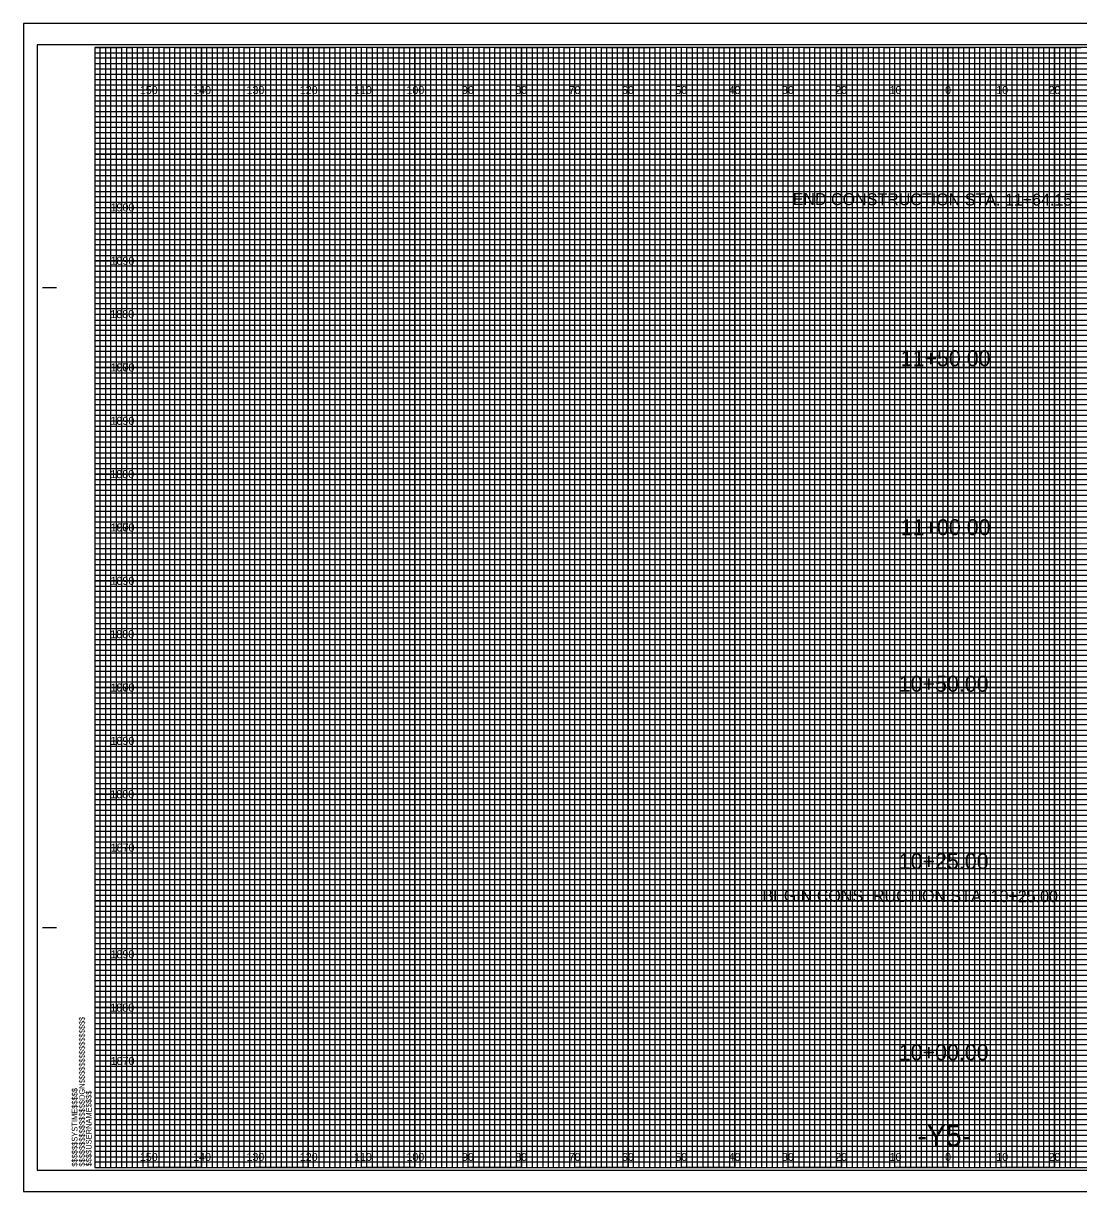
# Model space of a CAD drawing. Extents: x -13 to 323, y -4 to 214.
# Drawn here: x -13.4 to 184.5, y -4.5 to 214.5 of the extents above; entities that cross this region are included whole.
import ezdxf

# ---------------------------------------------------------------- set-up
doc = ezdxf.new("R2010")
doc.units = 0
for name, color, linetype in [('Prop XS Alignment Label', 7, 'Continuous'), ('Prop XS Elevation Labels', 7, 'Continuous'), ('Prop XS Offset Labels', 7, 'Continuous'), ('Prop XS SE Text', 7, 'Continuous'), ('Prop XS Station Labels', 7, 'Continuous'), ('Sheet Cross Section CELL', 7, 'Continuous'), ('Sheet Cross Section Grid Major CELL', 7, 'Continuous'), ('Sheet Cross Section Grid Middle CELL', 7, 'Continuous'), ('Sheet Cross Section Grid Minor 1 CELL', 7, 'Continuous'), ('Sheet Cross Section Grid Minor 2 CELL', 7, 'Continuous'), ('Sheet Cutting Line CELL', 7, 'Continuous'), ('Sheet DOT Grid CELL', 7, 'Continuous'), ('Sheet Plot Border Inside CELL', 7, 'Continuous'), ('Sheet Plot Border Outside CELL', 7, 'Continuous')]:
    doc.layers.add(name, color=color, linetype=linetype)

msp = doc.modelspace()

# ---------------------------------------------------------------- linework, layer by layer
at = {"layer": 'Sheet Cross Section CELL'}
for p, q in [((-9.8, 165), (-7.3, 165)), ((-9.7, 165), (-7.2, 165)), ((-9.8, 45), (-7.3, 45)), ((-9.7, 45), (-7.2, 45))]:
    msp.add_line(p, q, dxfattribs=at)
msp.add_lwpolyline([(320, 210), (0, 210), (0, 0), (320, 0)], close=True, dxfattribs=at)
at = {"layer": 'Sheet Cross Section Grid Major CELL'}
for p, q in [((10, 210), (0, 210)), ((10, 0), (10, 210)), ((30, 210), (20, 210)), ((20, 210), (20, 0)), ((30, 0), (30, 210)), ((50, 210), (40, 210)), ((40, 210), (40, 0)), ((50, 0), (50, 210)), ((70, 210), (60, 210)), ((60, 210), (60, 0)), ((70, 0), (70, 210)), ((90, 210), (80, 210)), ((80, 210), (80, 0)), ((90, 0), (90, 210)), ((110, 210), (100, 210)), ((100, 210), (100, 0)), ((110, 0), (110, 210)), ((130, 210), (120, 210)), ((120, 210), (120, 0)), ((130, 0), (130, 210)), ((150, 210), (140, 210)), ((140, 210), (140, 0)), ((150, 0), (150, 210)), ((170, 210), (160, 210)), ((160, 210), (160, 0)), ((170, 0), (170, 210)), ((190, 210), (180, 210)), ((180, 210), (180, 0)), ((20, 0), (10, 0)), ((40, 0), (30, 0)), ((60, 0), (50, 0)), ((80, 0), (70, 0)), ((100, 0), (90, 0)), ((120, 0), (110, 0)), ((140, 0), (130, 0)), ((160, 0), (150, 0)), ((180, 0), (170, 0))]:
    msp.add_line(p, q, dxfattribs=at)
for points in [[(0, 200), (320, 200), (320, 190), (0, 190)], [(0, 180), (320, 180), (320, 170), (0, 170)], [(0, 160), (320, 160), (320, 150), (0, 150)], [(0, 140), (320, 140), (320, 130), (0, 130)], [(0, 120), (320, 120), (320, 110), (0, 110)], [(0, 100), (320, 100), (320, 90), (0, 90)], [(0, 80), (320, 80), (320, 70), (0, 70)], [(0, 60), (320, 60), (320, 50), (0, 50)], [(0, 40), (320, 40), (320, 30), (0, 30)], [(0, 20), (320, 20), (320, 10), (0, 10)]]:
    msp.add_lwpolyline(points, dxfattribs=at)
at = {"layer": 'Sheet Cross Section Grid Middle CELL'}
for points in [[(0, 210), (5, 210), (5, 0), (15, 0), (15, 210), (25, 210), (25, 0), (35, 0), (35, 210), (45, 210), (45, 0), (55, 0), (55, 210), (65, 210), (65, 0), (75, 0), (75, 210), (85, 210), (85, 0), (95, 0), (95, 210), (105, 210), (105, 0), (115, 0), (115, 210), (125, 210), (125, 0), (135, 0), (135, 210), (145, 210), (145, 0), (155, 0), (155, 210), (165, 210), (165, 0), (175, 0), (175, 210), (185, 210)], [(0, 205), (275, 205)], [(0, 185), (320, 185), (320, 195), (0, 195)], [(0, 165), (320, 165), (320, 175), (0, 175)], [(0, 145), (320, 145), (320, 155), (0, 155)], [(0, 125), (320, 125), (320, 135), (0, 135)], [(0, 105), (320, 105), (320, 115), (0, 115)], [(0, 85), (320, 85), (320, 95), (0, 95)], [(0, 65), (320, 65), (320, 75), (0, 75)], [(0, 45), (320, 45), (320, 55), (0, 55)], [(0, 25), (320, 25), (320, 35), (0, 35)], [(0, 5), (320, 5), (320, 15), (0, 15)]]:
    msp.add_lwpolyline(points, dxfattribs=at)
at = {"layer": 'Sheet Cross Section Grid Minor 1 CELL'}
for p, q in [((0, 209), (260, 209)), ((260, 207.98), (0, 207.98)), ((0, 207.98), (0, 207)), ((0, 207), (260, 207)), ((260, 205.89), (0, 205.89)), ((0, 205.89), (0, 204)), ((0, 204), (320, 204))]:
    msp.add_line(p, q, dxfattribs=at)
for points in [[(0, 203), (270, 203), (320, 203), (320, 202), (0, 202)], [(0, 201), (320, 201), (320, 199), (0, 199)], [(0, 198), (320, 198), (320, 197), (0, 196.98)], [(0, 196), (320, 196), (320, 194), (0, 194)], [(0, 193), (320, 193), (320, 192), (0, 192)], [(0, 191), (320, 191), (320, 189), (0, 189)], [(0, 188), (320, 188), (320, 187), (0, 187)], [(0, 186), (320, 186), (320, 184), (0, 184)], [(0, 183), (320, 183), (320, 182), (0, 182)], [(0, 181), (320, 181), (320, 179), (0, 179)], [(0, 178), (320, 178), (320, 177), (0, 177)], [(0, 176), (320, 176), (320, 173.95), (320, 173), (320, 172), (0, 172)], [(0, 174), (320, 174), (320, 173), (0, 173)], [(0, 171), (320, 171), (320, 169), (0, 169.03)], [(0, 169.03), (320, 169), (320, 168), (0, 168)], [(0, 167), (320, 167), (320, 166), (0, 166)], [(0, 164), (320, 164), (320, 163), (0, 163)], [(0, 162), (320, 162), (320, 161), (0, 161)], [(-0.07, 158.89), (320, 158.89), (320, 157.88), (-0.07, 157.88)], [(0, 157), (320, 157), (320, 156), (0, 156)], [(0, 154), (320, 154), (320, 153), (0, 153)], [(0, 152), (320, 152), (320, 151), (0, 151)], [(0, 149), (320, 149), (320, 148), (0, 148)], [(0, 147), (320, 147), (320, 146), (0, 146)], [(0, 144), (320, 144), (320, 143), (0, 143)], [(0, 142), (320, 142), (320, 141), (0, 141)], [(0, 139), (320, 139), (319.99, 137.98), (0, 138)], [(0, 137), (320, 137), (320, 136), (0, 136)], [(0, 134), (320, 134), (320, 133), (0, 133)], [(0, 132), (320, 132), (320, 131), (0, 131)], [(0, 129), (320, 129), (320, 128), (0, 128)], [(0, 127), (320, 127), (320, 126), (0, 126)], [(0, 124), (320, 124), (320, 123), (0, 123)], [(0, 122), (320, 122), (320, 121), (0, 121)], [(0, 119), (320, 119), (320, 118), (0, 118)], [(0, 116.99), (320.07, 116.91), (320, 116), (0, 116)], [(0, 114), (320, 114), (320, 113), (0, 113)], [(0, 112), (320, 112), (320, 111), (0, 111)], [(0, 109), (320, 109), (320, 108), (0, 108)], [(0, 107), (320, 107), (320, 106), (0, 106)], [(0, 104), (320, 104), (320, 103), (0, 103)], [(0, 102), (320, 102), (320, 101), (0, 101)], [(0, 99), (320, 99), (320, 98), (0, 98)], [(0, 97), (320, 97), (320, 96), (0, 96)], [(0, 94), (320, 94), (320, 93), (0, 93)], [(0, 92), (320, 92), (320, 91), (0, 91)], [(0, 89), (320, 89), (320, 88), (0, 88)], [(0, 87), (320, 87), (320, 86), (0, 86)], [(0, 84), (320, 84), (320, 83), (0, 83)], [(0, 82), (320, 82), (320, 81), (0, 81)], [(0, 79), (320, 79), (319.99, 77.98), (0, 78)], [(0, 77), (320, 77), (320, 76), (0, 76)], [(0, 74), (320, 74), (320, 73), (0, 73)], [(0, 72), (320, 72), (320, 71), (0, 71)], [(0, 69), (320, 69), (320, 68), (0, 68)], [(0, 67), (320, 67), (320, 66), (0, 66)], [(0, 64), (320, 64), (320, 63), (0, 63)], [(0, 62), (320, 62), (320, 61), (0, 61)], [(0, 59), (320, 59), (320, 58), (0, 58)], [(0, 56.99), (320.07, 56.91), (320, 56), (0, 56)], [(0, 54), (320, 54), (320, 53), (0, 53)], [(0, 52), (320, 52), (320, 51), (0, 51)], [(0, 49), (320, 49), (320, 48), (0, 48)], [(0, 47), (320, 47), (320, 46), (0, 46)], [(0, 44), (320, 44), (320, 43), (0, 43)], [(0, 42), (320, 42), (320, 41), (0, 41)], [(0, 39), (320, 39), (320, 38), (0, 38)], [(0, 37), (320, 37), (320, 36), (0, 36)], [(0, 34), (320, 34), (320, 33), (0, 33)], [(0, 32), (320, 32), (320, 31), (0, 31)], [(0, 29), (320, 29), (320, 28), (0, 28)], [(0, 27), (320, 27), (320, 26), (0, 26)], [(0, 24), (320, 24), (320, 23), (0, 23)], [(0, 22), (320, 22), (320, 21), (0, 21)], [(0, 19), (320, 19), (320, 18), (0, 18)], [(0, 17), (320, 17), (320, 16), (0, 16)], [(0, 14), (320, 14), (320, 13), (0, 13)], [(0, 12), (320, 12), (320, 11), (0, 11)], [(0, 9), (320, 9), (320, 8), (0, 8)], [(0, 7), (320, 7), (320, 6), (0, 6)], [(0, 4), (320, 4), (320, 3), (0, 3)], [(0, 2), (320, 2), (320, 1), (0, 1)]]:
    msp.add_lwpolyline(points, dxfattribs=at)
at = {"layer": 'Sheet Cross Section Grid Minor 2 CELL'}
for points in [[(0, 0), (1, 0), (1, 210), (2, 210), (2, 0)], [(2, 0), (3, 0), (3, 210), (4, 210), (4, 0)], [(5, 0), (6, 0), (6, 210), (7, 210), (7, 0)], [(7, 0), (8, 0), (8, 210), (9, 210), (9, 0)], [(10, 0), (11, 0), (11, 210), (12, 210), (12, 0)], [(12, 0), (13, 0), (13, 210), (14, 210), (14, 0)], [(15, 0), (16, 0), (16, 210), (17, 210), (17, 0)], [(17, 0), (18, 0), (18, 210), (19, 210), (19, 0)], [(20, 0), (21, 0), (21, 210), (22, 210), (22, 0)], [(22, 0), (23, 0), (23, 210), (24, 210), (24, 0)], [(25, 0), (26, 0), (26, 210), (27, 210), (27, 0)], [(27, 0), (28, 0), (28, 210), (29, 210), (29, 0)], [(30, 0), (31, 0), (31, 210), (32, 210), (32, 0)], [(32, 0), (33, 0), (33, 210), (34, 210), (34, 0)], [(35, 0), (36, 0), (36, 210), (37, 210), (37, 0)], [(37, 0), (38, 0), (38, 210), (39, 210), (39, 0)], [(40, 0), (41, 0), (41, 210), (42, 210), (42, 0)], [(42, 0), (43, 0), (43, 210), (44, 210), (44, 0)], [(45, 0), (46, 0), (46, 210), (47, 210), (47, 0)], [(47, 0), (48, 0), (48, 210), (49, 210), (49, 0)], [(50, 0), (51, 0), (51, 210), (52, 210), (52, 0)], [(52, 0), (53, 0), (53, 210), (54, 210), (54, 0)], [(55, 0), (56, 0), (56, 210), (57, 210), (57, 0)], [(57, 0), (58, 0), (58, 210), (59, 210), (59, 0)], [(60, 0), (61, 0), (61, 210), (62, 210), (62, 0)], [(62, 0), (63, 0), (63, 210), (64, 210), (64, 0)], [(65, 0), (66, 0), (66, 210), (67, 210), (67, 0)], [(67, 0), (68, 0), (68, 210), (69, 210), (69, 0)], [(70, 0), (71, 0), (71, 210), (72, 210), (72, 0)], [(72, 0), (73, 0), (73, 210), (74, 210), (74, 0)], [(75, 0), (76, 0), (76, 210), (77, 210), (77, 0)], [(77, 0), (78, 0), (78, 210), (79, 210), (79, 0)], [(80, 0), (81, 0), (81, 210), (82, 210), (82, 0)], [(82, 0), (83, 0), (83, 210), (84, 210), (84, 0)], [(85, 0), (86, 0), (86, 210), (87, 210), (87, 0)], [(87, 0), (88, 0), (88, 210), (89, 210), (89, 0)], [(90, 0), (91, 0), (91, 210), (92, 210), (92, 0)], [(92, 0), (93, 0), (93, 210), (94, 210), (94, 0)], [(95, 0), (96, 0), (96, 210), (97, 210), (97, 0)], [(97, 0), (98, 0), (98, 210), (99, 210), (99, 0)], [(100, 0), (101, 0), (101, 210), (102, 210), (102, 0)], [(102, 0), (103, 0), (103, 210), (104, 210), (104, 0)], [(105, 0), (106, 0), (106, 210), (107, 210), (107, 0)], [(107, 0), (108, 0), (108, 210), (109, 210), (109, 0)], [(110, 0), (111, 0), (111, 210), (112, 210), (112, 0)], [(112, 0), (113, 0), (113, 210), (114, 210), (114, 0)], [(115, 0), (116, 0), (116, 210), (117, 210), (117, 0)], [(117, 0), (118, 0), (118, 210), (119, 210), (119, 0)], [(120, 0), (121, 0), (121, 210), (122, 210), (122, 0)], [(122, 0), (123, 0), (123, 210), (124, 210), (124, 0)], [(125, 0), (126, 0), (126, 210), (127, 210), (127, 0)], [(127, 0), (128, 0), (128, 210), (129, 210), (129, 0)], [(130, 0), (131, 0), (131, 210), (132, 210), (132, 0)], [(132, 0), (133, 0), (133, 210), (134, 210), (134, 0)], [(135, 0), (136, 0), (136, 210), (137, 210), (137, 0)], [(137, 0), (138, 0), (138, 210), (139, 210), (139, 0)], [(140, 0), (141, 0), (141, 210), (142, 210), (142, 0)], [(142, 0), (143, 0), (143, 210), (144, 210), (144, 0)], [(145, 0), (146, 0), (146, 210), (147, 210), (147, 0)], [(147, 0), (148, 0), (148, 210), (149, 210), (149, 0)], [(150, 0), (151, 0), (151, 210), (152, 210), (152, 0)], [(152, 0), (153, 0), (153, 210), (154, 210), (154, 0)], [(155, 0), (156, 0), (156, 210), (157, 210), (157, 0)], [(157, 0), (158, 0), (158, 210), (159, 210), (159, 0)], [(160, 0), (161, 0), (161, 210), (162, 210), (162, 0)], [(162, 0), (163, 0), (163, 210), (164, 210), (164, 0)], [(165, 0), (166, 0), (166, 210), (167, 210), (167, 0)], [(167, 0), (168, 0), (168, 210), (169, 210), (169, 0)], [(170, 0), (171, 0), (171, 210), (172, 210), (172, 0)], [(172, 0), (173, 0), (173, 210), (174, 210), (174, 0)], [(175, 0), (176, 0), (176, 210), (177, 210), (177, 0)], [(177, 0), (178, 0), (178, 210), (179, 210), (179, 0)], [(180, 0), (181, 0), (181, 210), (182, 210), (182, 0)], [(182, 0), (183, 0), (183, 210), (184, 210), (184, 0)]]:
    msp.add_lwpolyline(points, dxfattribs=at)
at = {"layer": 'Sheet Cutting Line CELL'}
for p, q in [((323.3, 214.5), (-13.4, 214.5)), ((-13.4, 214.5), (-13.4, -4.5)), ((-13.4, -4.5), (323.3, -4.5))]:
    msp.add_line(p, q, dxfattribs=at)
at = {"layer": 'Sheet DOT Grid CELL'}
for p, q in [((10, 0), (10, 210)), ((20, 0), (20, 210)), ((30, 0), (30, 210)), ((40, 0), (40, 210)), ((50, 0), (50, 210)), ((60, 0), (60, 210)), ((70, 0), (70, 210)), ((80, 0), (80, 210)), ((90, 0), (90, 210)), ((100, 0), (100, 210)), ((110, 0), (110, 210)), ((120, 0), (120, 210)), ((130, 0), (130, 210)), ((140, 0), (140, 210)), ((150, 0), (150, 210)), ((160, 0), (160, 210)), ((170, 0), (170, 210)), ((180, 0), (180, 210)), ((0, 200), (320, 200)), ((0, 190), (320, 190)), ((0, 180), (320, 180)), ((0, 170), (320, 170)), ((0, 160), (320, 160)), ((0, 150), (320, 150)), ((0, 140), (320, 140)), ((0, 130), (320, 130)), ((0, 120), (320, 120)), ((0, 110), (320, 110)), ((0, 100), (320, 100)), ((0, 90), (320, 90)), ((0, 80), (320, 80)), ((0, 70), (320, 70)), ((0, 60), (320, 60)), ((0, 50), (320, 50)), ((0, 40), (320, 40)), ((0, 30), (320, 30)), ((0, 20), (320, 20)), ((0, 10), (320, 10))]:
    msp.add_line(p, q, dxfattribs=at)
at = {"layer": 'Sheet Plot Border Inside CELL'}
msp.add_lwpolyline([(-10.8, -0.5), (322.4, -0.5), (322.4, 210.5), (-10.8, 210.5)], close=True, dxfattribs=at)
at = {"layer": 'Sheet Plot Border Outside CELL'}
msp.add_lwpolyline([(-13.4, -4.5), (323.3, -4.5), (323.3, 214.5), (-13.4, 214.5)], close=True, dxfattribs=at)

# ---------------------------------------------------------------- texts
at = {"layer": 'Prop XS Alignment Label'}
msp.add_text('-Y5-', height=4, dxfattribs=at).set_placement((154.25, 4))
at = {"layer": 'Prop XS Elevation Labels'}
for s, p in [('1900', (2.95, 179.25)), ('1890', (2.95, 169.25)), ('1880', (2.92, 159.25)), ('1900', (2.95, 149.25)), ('1870', (2.98, 149.25)), ('1890', (2.95, 139.25)), ('1880', (2.92, 129.25)), ('1900', (2.95, 119.25)), ('1870', (2.98, 119.25)), ('1890', (2.95, 109.25)), ('1880', (2.92, 99.25)), ('1900', (2.95, 89.25)), ('1870', (2.98, 89.25)), ('1890', (2.95, 79.25)), ('1880', (2.92, 69.25)), ('1870', (2.98, 59.25)), ('1890', (2.95, 39.25)), ('1880', (2.92, 29.25)), ('1870', (2.98, 19.25))]:
    msp.add_text(s, height=1.5, dxfattribs=at).set_placement(p)
at = {"layer": 'Prop XS Offset Labels'}
for s, p in [('150', (8.44, 201.25)), ('140', (18.44, 201.25)), ('130', (28.44, 201.25)), ('120', (38.44, 201.25)), ('110', (48.62, 201.25)), ('100', (58.44, 201.25)), ('90', (68.86, 201.25)), ('80', (78.86, 201.25)), ('70', (88.86, 201.25)), ('60', (98.86, 201.25)), ('50', (108.86, 201.25)), ('40', (118.86, 201.25)), ('30', (128.86, 201.25)), ('20', (138.86, 201.25)), ('10', (149.04, 201.25)), ('0', (159.45, 201.25)), ('0', (159.45, 201.25)), ('10', (169.04, 201.25)), ('20', (178.86, 201.25)), ('150', (8.44, 1.25)), ('140', (18.44, 1.25)), ('130', (28.44, 1.25)), ('120', (38.44, 1.25)), ('110', (48.62, 1.25)), ('100', (58.44, 1.25)), ('90', (68.86, 1.25)), ('80', (78.86, 1.25)), ('70', (88.86, 1.25)), ('60', (98.86, 1.25)), ('50', (108.86, 1.25)), ('40', (118.86, 1.25)), ('30', (128.86, 1.25)), ('20', (138.86, 1.25)), ('10', (149.04, 1.25)), ('0', (159.45, 1.25)), ('0', (159.45, 1.25)), ('10', (169.04, 1.25)), ('20', (178.86, 1.25))]:
    msp.add_text(s, height=1.5, dxfattribs=at).set_placement(p)
at = {"layer": 'Prop XS SE Text'}
for s, p in [('END CONSTRUCTION STA. 11+64.15', (130.88, 180.45)), ('BEGIN CONSTRUCTION STA. 10+25.00', (125.19, 49.88))]:
    msp.add_text(s, height=2.25, rotation=359.86, dxfattribs=at).set_placement(p)
at = {"layer": 'Prop XS Station Labels'}
for s, p in [('11+50.00', (151.13, 150.23)), ('11+00.00', (151.13, 118.55)), ('10+50.00', (150.77, 89.21)), ('10+25.00', (150.77, 55.95)), ('10+00.00', (150.77, 20.12))]:
    msp.add_text(s, height=3, dxfattribs=at).set_placement(p)
at = {"layer": 'Sheet Cross Section CELL'}
for s, p in [('$$$$$$$$$$$$$$$$DGN$$$$$$$$$$$$$$$$', (-1.88, 0.18)), ('$$$$$$SYSTIME$$$$$', (-3.26, 0.18)), ('$$$$USERNAME$$$$', (-0.62, 0.23))]:
    msp.add_text(s, height=1.05, rotation=90, dxfattribs=at).set_placement(p)

doc.saveas('drawing.dxf')
